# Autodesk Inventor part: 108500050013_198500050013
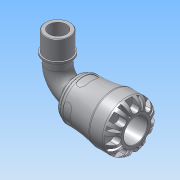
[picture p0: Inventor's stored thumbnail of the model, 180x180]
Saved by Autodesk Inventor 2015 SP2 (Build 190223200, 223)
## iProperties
Created: 2016-12
Part Number: 108500050013_198500050013
Material: PVC-Piping
Description: PLASSON 90° ELBOW WITH THREADED MALE OFFTAKE 50-1.1/4" SERIES 1
Document SubType Name: Modeling
Designer: KIM
Mass: 664.223 g
Surface Area: 733.008 cm^2
Volume: 474.445 cm^3
Density: 1.4 g/cm^3
Appearance: Smooth - White
Author: KIM
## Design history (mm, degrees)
derived "1085.ipt"
feature "Solid1::1085.ipt"
tag "TaggingFeature1"
body "Solid1"
other parameters: "d1" = 33.18, "d3" = 62.5, "d4" = 85, "d8" = 72.25, "d13" = 9, "d14" = 9, "d15" = 0, "d17" = 360 deg, "d19" = 8 deg, "d20" = 1, "d21" = 1, "d22" = 8 deg, "d24" = 0, "d26" = 360 deg, "d33" = 8.5, "d43" = 66.3, "d51" = 0.85, "d54" = 17.5, "d55" = 11, "d57" = 17.64, "d58" = 0, "d74" = 0, "d78" = 79, "d82" = 1, "d115" = 360 deg, "d207" = 90 deg, "d228" = 14.875, "d247" = 1.7, "d248" = 4.74, "d268" = 39.7375, "d269" = 4.74, "d270" = 122, "d276" = 41.91, "d277" = 22, "d278" = 46.101, "d279" = 68, "d280" = 24.2, "d281" = 6.2865, "d283" = 37.719, "d286" = 0, "d287" = 0, "d288" = 29.337, "d290" = 14.2905, "d292" = 30 deg, "E_" = 85, "l_" = 79, "A_" = 122, "A_1" = 68, "l_2" = 22, "R_" = 41.91, "d9" = 11.25, "d11" = 85, "d12" = 62.5, "d289" = 29.337
